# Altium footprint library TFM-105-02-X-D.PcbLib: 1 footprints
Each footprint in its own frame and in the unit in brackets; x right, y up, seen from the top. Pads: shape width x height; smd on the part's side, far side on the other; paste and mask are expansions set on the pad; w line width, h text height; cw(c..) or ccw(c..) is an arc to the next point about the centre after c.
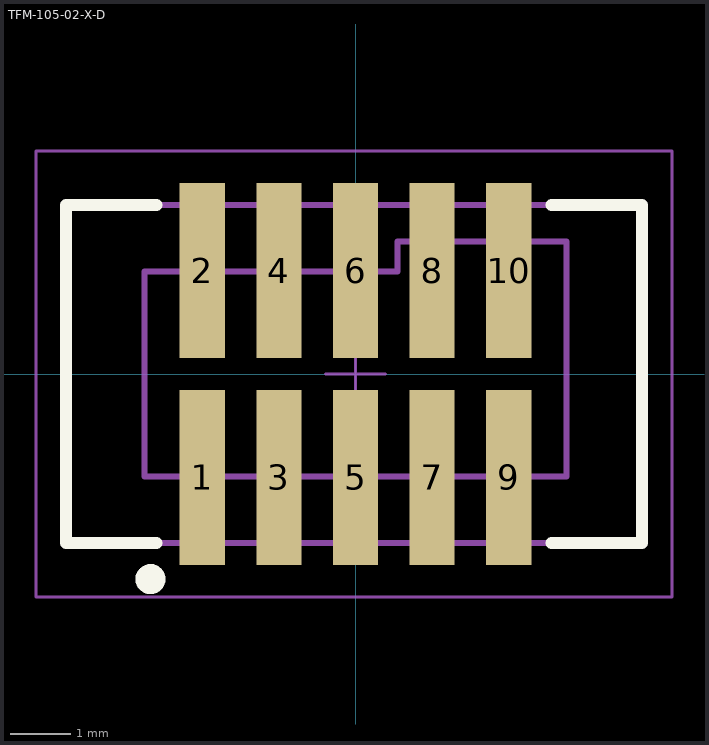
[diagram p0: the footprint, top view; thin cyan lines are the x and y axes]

## TFM-105-02-X-D [mm] "1.27mm pitch, 10 pin, terminal strip; SMT"
height 5.72
pads (10):
  rect 0.75x2.9 smd mask+0: 1(-2.54,-1.714) 2(-2.54,1.714) 3(-1.27,-1.714) 4(-1.27,1.714) 5(0,-1.714) 6(0,1.714) 7(1.27,-1.714) 8(1.27,1.714) 9(2.54,-1.714) 10(2.54,1.714)
Top Overlay:
  circle w0.25: c-3.4,-3.4 r0.125
  lines w0.2: -3.3,-2.8 -4.8,-2.8 -4.8,2.8 -3.3,2.8 ; 3.25,-2.8 4.75,-2.8 4.75,2.8 3.25,2.8
Mechanical 12:
  lines w0.001: -4.8,-2.8 -4.8,2.8 4.75,2.8 4.75,-2.8 -4.8,-2.8 ; -3.5,-1.7 -3.5,1.7 0.7,1.7 0.7,2.2 3.5,2.2 3.5,-1.7 -3.5,-1.7
Mechanical 13:
  lines w0.1: -4.8,-2.8 -4.8,2.8 4.75,2.8 4.75,-2.8 -4.8,-2.8 ; -3.5,-1.7 -3.5,1.7 0.7,1.7 0.7,2.2 3.5,2.2 3.5,-1.7 -3.5,-1.7
  text ".Designator" at 0,-0.127 h1.52
Mechanical 15:
  lines w0.05: -0.5,0 0.5,0 ; 0,-0.5 0,0.5 ; -5.3,-3.7 -5.3,3.7 5.25,3.7 5.25,-3.7 -5.3,-3.7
